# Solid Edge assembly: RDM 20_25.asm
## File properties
Title: Zylinder
Author: ahadarics
Template: iso metric assembly.asm
Last saved by: ahadarics
Revision: 12
Application: Solid Edge
Username: ahadarics
Dokumentum tartalom típus: 1
Document Number: RDM 20/25
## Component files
Kit_2.par
Profilrohr.par
Kolbenstange.par
Kit_1.par
Mutter_1.par
Mutter_2.par
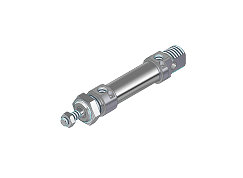
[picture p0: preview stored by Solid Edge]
